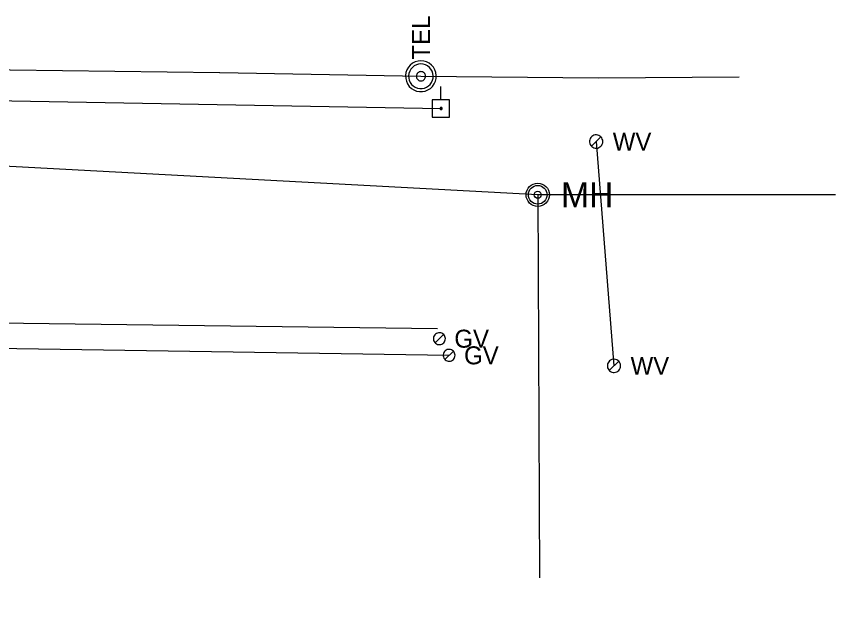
# Model space of a CAD drawing. Extents: x 596028 to 606371, y 330010 to 403088.
# Drawn here: x 605354.3 to 605530.1, y 332615.5 to 332741.8 of the extents above; entities that cross this region are included whole.
import ezdxf

# ---------------------------------------------------------------- set-up
doc = ezdxf.new("R2010")
doc.units = 0
for name, color, linetype in [('Default', 7, 'Continuous'), ('E_UTL_E', 7, 'Continuous'), ('E_UTL_E_UG', 7, 'Continuous'), ('E_UTL_EPowerPole', 7, 'Continuous'), ('E_UTL_G', 7, 'Continuous'), ('E_UTL_G_UG', 7, 'Continuous'), ('E_UTL_Overhead', 7, 'Continuous'), ('E_UTL_T_MH', 7, 'Continuous'), ('E_UTL_T_UG', 7, 'Continuous'), ('E_UTL_W', 7, 'Continuous'), ('E_UTL_W_UG', 7, 'Continuous')]:
    doc.layers.add(name, color=color, linetype=linetype)

# ---------------------------------------------------------------- blocks, each defined once
blk = doc.blocks.new('MH')
at = {"layer": 'Default'}
for radius in [15.2, 12.2, 4.57]:
    blk.add_circle((0, 0), radius, dxfattribs=at)
blk.add_text('MH', height=32.92, dxfattribs=at).set_placement((30.5, -16.5))

msp = doc.modelspace()

# ---------------------------------------------------------------- linework, layer by layer
at = {"layer": 'E_UTL_E_UG'}
for p, q in [((605164.12, 332719.76), (605466.18, 332703.6)), ((605466.18, 332703.6), (605530.08, 332703.62)), ((605466.18, 332703.6), (605466.55, 332621.41))]:
    msp.add_line(p, q, dxfattribs=at)
at = {"layer": 'E_UTL_EPowerPole'}
for points in [[(605445.4, 332723.89), (605445.4, 332726.79)], [(605447.25, 332723.89), (605443.56, 332723.89)], [(605443.56, 332723.89), (605443.56, 332720.19)], [(605447.25, 332720.19), (605447.25, 332723.89)], [(605445.67, 332722.04), (605445.67, 332722.09), (605445.66, 332722.13), (605445.64, 332722.17), (605445.61, 332722.21), (605445.57, 332722.24), (605445.53, 332722.26), (605445.49, 332722.27), (605445.45, 332722.28), (605445.4, 332722.28), (605445.36, 332722.27), (605445.32, 332722.25), (605445.28, 332722.22), (605445.25, 332722.19), (605445.22, 332722.15), (605445.21, 332722.11), (605445.2, 332722.07), (605445.2, 332722.02), (605445.21, 332721.98), (605445.22, 332721.93), (605445.25, 332721.9), (605445.28, 332721.86), (605445.32, 332721.84), (605445.36, 332721.82), (605445.4, 332721.81), (605445.45, 332721.8), (605445.49, 332721.81), (605445.53, 332721.83), (605445.57, 332721.85), (605445.61, 332721.88), (605445.64, 332721.91), (605445.66, 332721.95), (605445.67, 332722), (605445.67, 332722.04)], [(605443.56, 332720.19), (605447.25, 332720.19)]]:
    msp.add_lwpolyline(points, dxfattribs=at)
at = {"layer": 'E_UTL_G'}
for points in [[(605446.36, 332672.71), (605446.34, 332672.95), (605446.27, 332673.18), (605446.16, 332673.4), (605446, 332673.59), (605445.82, 332673.75), (605445.61, 332673.88), (605445.38, 332673.95), (605445.14, 332673.99), (605444.89, 332673.98), (605444.66, 332673.92), (605444.43, 332673.82), (605444.24, 332673.68), (605444.07, 332673.5), (605443.94, 332673.3), (605443.84, 332673.07), (605443.8, 332672.83), (605443.8, 332672.59), (605443.84, 332672.35), (605443.94, 332672.12), (605444.07, 332671.91), (605444.24, 332671.74), (605444.43, 332671.6), (605444.66, 332671.49), (605444.89, 332671.44), (605445.14, 332671.43), (605445.38, 332671.46), (605445.61, 332671.54), (605445.82, 332671.66), (605446, 332671.82), (605446.16, 332672.01), (605446.27, 332672.23), (605446.34, 332672.46), (605446.36, 332672.71)], [(605444.17, 332671.8), (605445.98, 332673.61)], [(605448.45, 332669.14), (605448.42, 332669.38), (605448.35, 332669.62), (605448.24, 332669.83), (605448.09, 332670.03), (605447.91, 332670.19), (605447.7, 332670.31), (605447.47, 332670.39), (605447.22, 332670.42), (605446.98, 332670.41), (605446.74, 332670.35), (605446.52, 332670.25), (605446.32, 332670.11), (605446.15, 332669.93), (605446.02, 332669.73), (605445.93, 332669.5), (605445.89, 332669.26), (605445.89, 332669.02), (605445.93, 332668.78), (605446.02, 332668.55), (605446.15, 332668.35), (605446.32, 332668.17), (605446.52, 332668.03), (605446.74, 332667.93), (605446.98, 332667.87), (605447.22, 332667.86), (605447.47, 332667.89), (605447.7, 332667.97), (605447.91, 332668.09), (605448.09, 332668.25), (605448.24, 332668.45), (605448.35, 332668.66), (605448.42, 332668.9), (605448.45, 332669.14)], [(605446.26, 332668.23), (605448.07, 332670.05)]]:
    msp.add_lwpolyline(points, dxfattribs=at)
at = {"layer": 'E_UTL_G_UG'}
msp.add_line((605258.6, 332677.26), (605444.7, 332674.89), dxfattribs=at)
msp.add_lwpolyline([(604999.13, 332234.39), (604999.86, 332312.33), (605000.09, 332338.31), (605000.11, 332381.53), (605000.58, 332421.33), (605001.25, 332517.82), (605001.72, 332543.05), (605001.99, 332582.9), (605009.14, 332588.51), (605017.08, 332595.02), (605025.17, 332603.98), (605053.2, 332636.73), (605068.82, 332651.42), (605069.91, 332651.64), (605092.37, 332651), (605098.99, 332656), (605103.96, 332660.87), (605106.76, 332663.11), (605116.6, 332673.18), (605136.39, 332673.6), (605163.97, 332673.14), (605215.25, 332672.77), (605447.16, 332669.14)], dxfattribs=at)
at = {"layer": 'E_UTL_Overhead'}
msp.add_lwpolyline([(605176.94, 332731.2), (605251.67, 332726.56), (605281.19, 332725), (605445.44, 332722.04)], dxfattribs=at)
at = {"layer": 'E_UTL_T_MH'}
for points in [[(605441.12, 332732.25), (605440.49, 332732.19), (605439.89, 332732.02), (605439.33, 332731.73), (605438.84, 332731.34), (605438.43, 332730.87), (605438.11, 332730.32), (605437.91, 332729.73), (605437.82, 332729.11), (605437.85, 332728.48), (605438, 332727.87), (605438.26, 332727.3), (605438.62, 332726.79), (605439.08, 332726.36), (605439.6, 332726.02), (605440.19, 332725.79), (605440.8, 332725.67), (605441.43, 332725.67), (605442.05, 332725.79), (605442.63, 332726.02), (605443.16, 332726.36), (605443.61, 332726.79), (605443.97, 332727.3), (605444.23, 332727.87), (605444.38, 332728.48), (605444.41, 332729.11), (605444.32, 332729.73), (605444.12, 332730.32), (605443.8, 332730.87), (605443.39, 332731.34), (605442.9, 332731.73), (605442.34, 332732.02), (605441.74, 332732.19), (605441.12, 332732.25)], [(605441.12, 332731.59), (605440.62, 332731.54), (605440.13, 332731.4), (605439.69, 332731.17), (605439.29, 332730.86), (605438.97, 332730.48), (605438.71, 332730.05), (605438.55, 332729.57), (605438.48, 332729.08), (605438.5, 332728.58), (605438.62, 332728.09), (605438.83, 332727.63), (605439.12, 332727.22), (605439.48, 332726.88), (605439.91, 332726.61), (605440.37, 332726.42), (605440.87, 332726.32), (605441.37, 332726.32), (605441.86, 332726.42), (605442.33, 332726.61), (605442.75, 332726.88), (605443.11, 332727.22), (605443.4, 332727.63), (605443.61, 332728.09), (605443.73, 332728.58), (605443.75, 332729.08), (605443.68, 332729.57), (605443.52, 332730.05), (605443.27, 332730.48), (605442.94, 332730.86), (605442.54, 332731.17), (605442.1, 332731.4), (605441.62, 332731.54), (605441.12, 332731.59)], [(605441.12, 332729.94), (605440.93, 332729.92), (605440.75, 332729.87), (605440.58, 332729.79), (605440.43, 332729.67), (605440.31, 332729.53), (605440.22, 332729.36), (605440.15, 332729.19), (605440.13, 332729), (605440.14, 332728.81), (605440.18, 332728.63), (605440.26, 332728.46), (605440.37, 332728.3), (605440.5, 332728.17), (605440.66, 332728.07), (605440.84, 332728), (605441.02, 332727.97), (605441.21, 332727.97), (605441.4, 332728), (605441.57, 332728.07), (605441.73, 332728.17), (605441.86, 332728.3), (605441.97, 332728.46), (605442.05, 332728.63), (605442.1, 332728.81), (605442.1, 332729), (605442.08, 332729.19), (605442.02, 332729.36), (605441.92, 332729.53), (605441.8, 332729.67), (605441.65, 332729.79), (605441.48, 332729.87), (605441.3, 332729.92), (605441.12, 332729.94)]]:
    msp.add_lwpolyline(points, dxfattribs=at)
at = {"layer": 'E_UTL_T_UG'}
msp.add_lwpolyline([(605114.2, 332728.34), (605148.01, 332733.35), (605177.23, 332732.99), (605191.32, 332732.89), (605214.93, 332733.52), (605275.9, 332731.38), (605316.06, 332730.67), (605353.02, 332730.35), (605397.93, 332729.76), (605398, 332729.79), (605441.12, 332728.95), (605479.18, 332728.65), (605509.36, 332728.83)], dxfattribs=at)
at = {"layer": 'E_UTL_W'}
for points in [[(605480.13, 332714.96), (605480.11, 332715.23), (605480.03, 332715.49), (605479.91, 332715.73), (605479.74, 332715.94), (605479.53, 332716.12), (605479.3, 332716.25), (605479.04, 332716.34), (605478.77, 332716.38), (605478.5, 332716.37), (605478.24, 332716.31), (605477.99, 332716.19), (605477.77, 332716.04), (605477.59, 332715.84), (605477.44, 332715.61), (605477.34, 332715.36), (605477.29, 332715.09), (605477.29, 332714.82), (605477.34, 332714.56), (605477.44, 332714.3), (605477.59, 332714.08), (605477.77, 332713.88), (605477.99, 332713.72), (605478.24, 332713.61), (605478.5, 332713.55), (605478.77, 332713.53), (605479.04, 332713.57), (605479.3, 332713.66), (605479.53, 332713.8), (605479.74, 332713.97), (605479.91, 332714.19), (605480.03, 332714.43), (605480.11, 332714.69), (605480.13, 332714.96)], [(605477.7, 332713.95), (605479.71, 332715.97)], [(605483.96, 332666.88), (605483.93, 332667.15), (605483.85, 332667.41), (605483.73, 332667.65), (605483.56, 332667.86), (605483.36, 332668.04), (605483.12, 332668.18), (605482.87, 332668.27), (605482.6, 332668.31), (605482.33, 332668.29), (605482.06, 332668.23), (605481.82, 332668.12), (605481.6, 332667.96), (605481.41, 332667.76), (605481.26, 332667.53), (605481.16, 332667.28), (605481.11, 332667.02), (605481.11, 332666.75), (605481.16, 332666.48), (605481.26, 332666.23), (605481.41, 332666), (605481.6, 332665.8), (605481.82, 332665.65), (605482.06, 332665.53), (605482.33, 332665.47), (605482.6, 332665.46), (605482.87, 332665.5), (605483.12, 332665.58), (605483.36, 332665.72), (605483.56, 332665.9), (605483.73, 332666.11), (605483.85, 332666.35), (605483.93, 332666.61), (605483.96, 332666.88)], [(605481.52, 332665.87), (605483.54, 332667.89)]]:
    msp.add_lwpolyline(points, dxfattribs=at)
at = {"layer": 'E_UTL_W_UG'}
msp.add_lwpolyline([(605478.71, 332714.96), (605482.53, 332666.88)], dxfattribs=at)

# ---------------------------------------------------------------- block references
at = {"layer": 'E_UTL_E', "xscale": 0.16404166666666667, "yscale": 0.16404166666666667}
msp.add_blockref('MH', (605466.17, 332703.55), dxfattribs=at)

# ---------------------------------------------------------------- texts
at = {"layer": 'E_UTL_G'}
for p in [(605448.28, 332670.78), (605450.37, 332667.21)]:
    msp.add_text('GV', height=3.85, dxfattribs=at).set_placement(p)
at = {"layer": 'E_UTL_T_MH'}
msp.add_text('TEL', height=3.849, rotation=90, dxfattribs=at).set_placement((605443.06, 332732.52))
at = {"layer": 'E_UTL_W'}
for p in [(605482.27, 332713.03), (605486.09, 332664.96)]:
    msp.add_text('WV', height=3.85, dxfattribs=at).set_placement(p)

doc.saveas('drawing.dxf')
